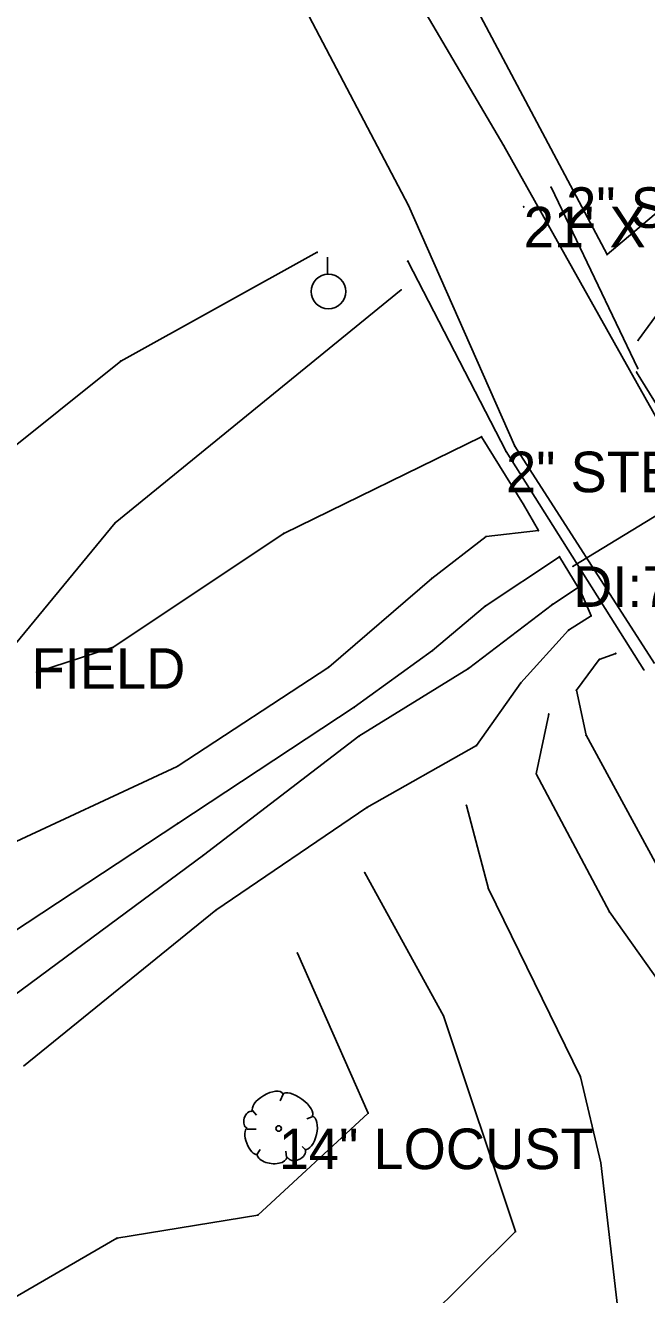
# Model space of a CAD drawing. Extents: x 1419505 to 1434054, y 1956910 to 1968644.
# Drawn here: x 1423011.2 to 1423087.7, y 1959040 to 1959196.4 of the extents above; entities that cross this region are included whole.
import ezdxf

# ---------------------------------------------------------------- set-up
doc = ezdxf.new("R2010")
doc.units = 0
for name, color, linetype in [('S_BREAKLINE', 7, 'Continuous'), ('S_DITCHLINE', 7, 'Continuous'), ('S_DRG_PT_SYM', 7, 'Continuous'), ('S_FENCE', 7, 'Continuous'), ('S_FENCE_ANNOT', 7, 'Continuous'), ('S_GATE_ANNOT', 7, 'Continuous'), ('S_GRAVEL_ROAD', 7, 'Continuous'), ('S_GRD_PT_SYM', 7, 'Continuous'), ('S_HEADWALL', 7, 'Continuous'), ('S_MSC_PT_SYM', 7, 'Continuous'), ('S_RDW_PT_SYM', 7, 'Continuous'), ('S_SIDE_DRAIN', 7, 'Continuous'), ('S_SIDE_DRAIN_ANNOT', 7, 'Continuous'), ('S_SURVEY_TEXT_ANNOT', 7, 'Continuous'), ('S_TREE', 7, 'Continuous'), ('S_TREE_ANNOT', 7, 'Continuous'), ('S_UTILITY_POLE', 7, 'Continuous')]:
    doc.layers.add(name, color=color, linetype=linetype)

msp = doc.modelspace()

# ---------------------------------------------------------------- linework, layer by layer
at = {"layer": 'S_BREAKLINE'}
for p, q in [((1423066.9272, 1959198.1301), (1423082.8213, 1959168.1511)), ((1423082.8213, 1959168.1511), (1423102.5315, 1959184.7692)), ((1423086.6625, 1959157.5914), (1423098.1723, 1959173.3905)), ((1423022.9164, 1959155.0183), (1423047.126, 1959168.4171)), ((1423022.2564, 1959135.109), (1423057.4626, 1959163.7828)), ((1422994.5276, 1959132.2688), (1423022.9164, 1959155.0183)), ((1423067.3583, 1959145.7077), (1423042.9967, 1959133.7819)), ((1423072.5376, 1959137.3621), (1423067.3583, 1959145.7077)), ((1423074.3627, 1959134.1599), (1423072.5376, 1959137.3621)), ((1422998.6778, 1959106.5561), (1423022.2564, 1959135.109)), ((1423042.9967, 1959133.7819), (1423022.0103, 1959119.77)), ((1423061.2399, 1959128.2445), (1423067.9153, 1959133.4009)), ((1423067.9153, 1959133.4009), (1423074.3627, 1959134.1599)), ((1423048.5511, 1959117.3138), (1423061.2399, 1959128.2445)), ((1423080.8521, 1959123.6222), (1423079.7661, 1959126.2424)), ((1423078.088, 1959121.8761), (1423080.8521, 1959123.6222)), ((1423072.2056, 1959115.3877), (1423078.088, 1959121.8761)), ((1423022.0103, 1959119.77), (1423012.5577, 1959116.6958)), ((1423081.8662, 1959118.2619), (1423083.9013, 1959119.0109)), ((1423029.8858, 1959105.094), (1423048.5511, 1959117.3138)), ((1423079.056, 1959114.4817), (1423081.8662, 1959118.2619)), ((1423066.7272, 1959107.6562), (1423072.2056, 1959115.3877)), ((1423080.2391, 1959108.9373), (1423079.056, 1959114.4817)), ((1423074.1077, 1959104.179), (1423075.6348, 1959111.5295)), ((1423089.7787, 1959091.4022), (1423080.2391, 1959108.9373)), ((1423053.2464, 1959100.0337), (1423066.7272, 1959107.6562)), ((1423000.908, 1959091.6272), (1423029.8858, 1959105.094)), ((1423083.1143, 1959087.1749), (1423074.1077, 1959104.179)), ((1423034.6522, 1959087.3959), (1423053.2464, 1959100.0337)), ((1423068.2213, 1959090.0191), (1423065.4961, 1959100.2827)), ((1423062.699, 1959074.3631), (1423052.9783, 1959092.0002)), ((1423079.5501, 1959066.8446), (1423068.2213, 1959090.0191)), ((1423010.9586, 1959068.1907), (1423034.6522, 1959087.3959)), ((1423097.3592, 1959067.1286), (1423083.1143, 1959087.1749)), ((1423053.4184, 1959062.4033), (1423044.6818, 1959082.1046)), ((1423071.5395, 1959047.7953), (1423062.699, 1959074.3631)), ((1423082.0782, 1959056.2559), (1423079.5501, 1959066.8446)), ((1423039.8265, 1959049.8425), (1423053.4184, 1959062.4033)), ((1423084.7974, 1959032.7634), (1423082.0782, 1959056.2559)), ((1423022.4534, 1959046.9853), (1423039.8265, 1959049.8425)), ((1422987.9141, 1959027.032), (1423022.4534, 1959046.9853)), ((1423056.3426, 1959032.7244), (1423071.5395, 1959047.7953))]:
    msp.add_line(p, q, dxfattribs=at)
at = {"layer": 'S_DITCHLINE'}
for p, q in [((1423076.9659, 1959130.9217), (1423067.8313, 1959124.8523)), ((1423079.284, 1959127.1275), (1423076.9659, 1959130.9217)), ((1423076.0958, 1959125.0493), (1423079.284, 1959127.1275)), ((1423065.7502, 1959117.1468), (1423076.0958, 1959125.0493)), ((1423067.8313, 1959124.8523), (1423061.3359, 1959119.361)), ((1423051.6803, 1959112.3905), (1423061.3409, 1959119.38)), ((1423052.2533, 1959108.8193), (1423065.7502, 1959117.1468)), ((1423029.9539, 1959098.0626), (1423051.6803, 1959112.3905)), ((1423033.1021, 1959094.1543), (1423052.2533, 1959108.8193)), ((1423001.755, 1959079.5054), (1423029.9539, 1959098.0626)), ((1423005.2653, 1959073.577), (1423033.1021, 1959094.1543))]:
    msp.add_line(p, q, dxfattribs=at)
at = {"layer": 'S_DRG_PT_SYM'}
msp.add_lwpolyline([(1423078.642, 1959129.7416), (1423078.642, 1959129.7916), (1423078.642, 1959129.7416), (1423078.592, 1959129.7416), (1423078.642, 1959129.7416), (1423078.642, 1959129.6916), (1423078.642, 1959129.7416), (1423078.692, 1959129.7416)], dxfattribs=at)
at = {"layer": 'S_FENCE'}
for p, q in [((1423075.9258, 1959176.4207), (1423086.5975, 1959154.1162)), ((1423070.3805, 1959143.8636), (1423058.2957, 1959167.3221))]:
    msp.add_line(p, q, dxfattribs=at)
at = {"layer": 'S_GRAVEL_ROAD'}
for p, q in [((1423070.1264, 1959181.533), (1423042.2936, 1959228.774)), ((1423058.3767, 1959174.1935), (1423036.7293, 1959215.3232)), ((1423101.5895, 1959125.3534), (1423070.1264, 1959181.533)), ((1423071.4495, 1959144.5446), (1423058.3767, 1959174.1935)), ((1423088.6566, 1959117.7649), (1423071.4495, 1959144.5446))]:
    msp.add_line(p, q, dxfattribs=at)
at = {"layer": 'S_GRD_PT_SYM'}
for points in [[(1423047.126, 1959168.4171), (1423047.126, 1959168.4671), (1423047.126, 1959168.4171), (1423047.076, 1959168.4171), (1423047.126, 1959168.4171), (1423047.126, 1959168.3671), (1423047.126, 1959168.4171), (1423047.176, 1959168.4171)], [(1423082.8213, 1959168.1511), (1423082.8213, 1959168.2011), (1423082.8213, 1959168.1511), (1423082.7713, 1959168.1511), (1423082.8213, 1959168.1511), (1423082.8213, 1959168.1011), (1423082.8213, 1959168.1511), (1423082.8713, 1959168.1511)], [(1423057.4626, 1959163.7828), (1423057.4626, 1959163.8328), (1423057.4626, 1959163.7828), (1423057.4126, 1959163.7828), (1423057.4626, 1959163.7828), (1423057.4626, 1959163.7328), (1423057.4626, 1959163.7828), (1423057.5126, 1959163.7828)], [(1423086.6625, 1959157.5914), (1423086.6625, 1959157.6414), (1423086.6625, 1959157.5914), (1423086.6125, 1959157.5914), (1423086.6625, 1959157.5914), (1423086.6625, 1959157.5414), (1423086.6625, 1959157.5914), (1423086.7125, 1959157.5914)], [(1423022.9164, 1959155.0183), (1423022.9164, 1959155.0683), (1423022.9164, 1959155.0183), (1423022.8664, 1959155.0183), (1423022.9164, 1959155.0183), (1423022.9164, 1959154.9683), (1423022.9164, 1959155.0183), (1423022.9664, 1959155.0183)], [(1423067.3583, 1959145.7077), (1423067.3583, 1959145.7577), (1423067.3583, 1959145.7077), (1423067.3083, 1959145.7077), (1423067.3583, 1959145.7077), (1423067.3583, 1959145.6577), (1423067.3583, 1959145.7077), (1423067.4083, 1959145.7077)], [(1423072.5376, 1959137.3621), (1423072.5376, 1959137.4121), (1423072.5376, 1959137.3621), (1423072.4876, 1959137.3621), (1423072.5376, 1959137.3621), (1423072.5376, 1959137.3121), (1423072.5376, 1959137.3621), (1423072.5876, 1959137.3621)], [(1423022.2564, 1959135.109), (1423022.2564, 1959135.159), (1423022.2564, 1959135.109), (1423022.2064, 1959135.109), (1423022.2564, 1959135.109), (1423022.2564, 1959135.059), (1423022.2564, 1959135.109), (1423022.3064, 1959135.109)], [(1423042.9967, 1959133.7819), (1423042.9967, 1959133.8319), (1423042.9967, 1959133.7819), (1423042.9467, 1959133.7819), (1423042.9967, 1959133.7819), (1423042.9967, 1959133.7319), (1423042.9967, 1959133.7819), (1423043.0467, 1959133.7819)], [(1423067.9153, 1959133.4009), (1423067.9153, 1959133.4509), (1423067.9153, 1959133.4009), (1423067.8653, 1959133.4009), (1423067.9153, 1959133.4009), (1423067.9153, 1959133.3509), (1423067.9153, 1959133.4009), (1423067.9653, 1959133.4009)], [(1423074.3627, 1959134.1599), (1423074.3627, 1959134.2099), (1423074.3627, 1959134.1599), (1423074.3127, 1959134.1599), (1423074.3627, 1959134.1599), (1423074.3627, 1959134.1099), (1423074.3627, 1959134.1599), (1423074.4127, 1959134.1599)], [(1423076.9659, 1959130.9217), (1423076.9659, 1959130.9717), (1423076.9659, 1959130.9217), (1423076.9159, 1959130.9217), (1423076.9659, 1959130.9217), (1423076.9659, 1959130.8717), (1423076.9659, 1959130.9217), (1423077.0159, 1959130.9217)], [(1423061.2399, 1959128.2445), (1423061.2399, 1959128.2945), (1423061.2399, 1959128.2445), (1423061.1899, 1959128.2445), (1423061.2399, 1959128.2445), (1423061.2399, 1959128.1945), (1423061.2399, 1959128.2445), (1423061.2899, 1959128.2445)], [(1423079.284, 1959127.1275), (1423079.284, 1959127.1775), (1423079.284, 1959127.1275), (1423079.234, 1959127.1275), (1423079.284, 1959127.1275), (1423079.284, 1959127.0775), (1423079.284, 1959127.1275), (1423079.334, 1959127.1275)], [(1423067.8313, 1959124.8523), (1423067.8313, 1959124.9023), (1423067.8313, 1959124.8523), (1423067.7813, 1959124.8523), (1423067.8313, 1959124.8523), (1423067.8313, 1959124.8023), (1423067.8313, 1959124.8523), (1423067.8813, 1959124.8523)], [(1423076.0958, 1959125.0493), (1423076.0958, 1959125.0993), (1423076.0958, 1959125.0493), (1423076.0458, 1959125.0493), (1423076.0958, 1959125.0493), (1423076.0958, 1959124.9993), (1423076.0958, 1959125.0493), (1423076.1458, 1959125.0493)], [(1423079.7661, 1959126.2424), (1423079.7661, 1959126.2924), (1423079.7661, 1959126.2424), (1423079.7161, 1959126.2424), (1423079.7661, 1959126.2424), (1423079.7661, 1959126.1924), (1423079.7661, 1959126.2424), (1423079.8161, 1959126.2424)], [(1423080.8521, 1959123.6222), (1423080.8521, 1959123.6722), (1423080.8521, 1959123.6222), (1423080.8021, 1959123.6222), (1423080.8521, 1959123.6222), (1423080.8521, 1959123.5722), (1423080.8521, 1959123.6222), (1423080.9021, 1959123.6222)], [(1423078.088, 1959121.8761), (1423078.088, 1959121.9261), (1423078.088, 1959121.8761), (1423078.038, 1959121.8761), (1423078.088, 1959121.8761), (1423078.088, 1959121.8261), (1423078.088, 1959121.8761), (1423078.138, 1959121.8761)], [(1423022.0103, 1959119.77), (1423022.0103, 1959119.82), (1423022.0103, 1959119.77), (1423021.9603, 1959119.77), (1423022.0103, 1959119.77), (1423022.0103, 1959119.72), (1423022.0103, 1959119.77), (1423022.0603, 1959119.77)], [(1423061.3359, 1959119.361), (1423061.3359, 1959119.411), (1423061.3359, 1959119.361), (1423061.2859, 1959119.361), (1423061.3359, 1959119.361), (1423061.3359, 1959119.311), (1423061.3359, 1959119.361), (1423061.3859, 1959119.361)], [(1423061.3409, 1959119.38), (1423061.3409, 1959119.43), (1423061.3409, 1959119.38), (1423061.2909, 1959119.38), (1423061.3409, 1959119.38), (1423061.3409, 1959119.33), (1423061.3409, 1959119.38), (1423061.3909, 1959119.38)], [(1423083.9013, 1959119.0109), (1423083.9013, 1959119.0609), (1423083.9013, 1959119.0109), (1423083.8513, 1959119.0109), (1423083.9013, 1959119.0109), (1423083.9013, 1959118.9609), (1423083.9013, 1959119.0109), (1423083.9513, 1959119.0109)], [(1423048.5511, 1959117.3138), (1423048.5511, 1959117.3638), (1423048.5511, 1959117.3138), (1423048.5011, 1959117.3138), (1423048.5511, 1959117.3138), (1423048.5511, 1959117.2638), (1423048.5511, 1959117.3138), (1423048.6011, 1959117.3138)], [(1423065.7502, 1959117.1468), (1423065.7502, 1959117.1968), (1423065.7502, 1959117.1468), (1423065.7002, 1959117.1468), (1423065.7502, 1959117.1468), (1423065.7502, 1959117.0968), (1423065.7502, 1959117.1468), (1423065.8002, 1959117.1468)], [(1423081.8662, 1959118.2619), (1423081.8662, 1959118.3119), (1423081.8662, 1959118.2619), (1423081.8162, 1959118.2619), (1423081.8662, 1959118.2619), (1423081.8662, 1959118.2119), (1423081.8662, 1959118.2619), (1423081.9162, 1959118.2619)], [(1423012.5577, 1959116.6958), (1423012.5577, 1959116.7458), (1423012.5577, 1959116.6958), (1423012.5077, 1959116.6958), (1423012.5577, 1959116.6958), (1423012.5577, 1959116.6458), (1423012.5577, 1959116.6958), (1423012.6077, 1959116.6958)], [(1423072.2056, 1959115.3877), (1423072.2056, 1959115.4377), (1423072.2056, 1959115.3877), (1423072.1556, 1959115.3877), (1423072.2056, 1959115.3877), (1423072.2056, 1959115.3377), (1423072.2056, 1959115.3877), (1423072.2556, 1959115.3877)], [(1423079.056, 1959114.4817), (1423079.056, 1959114.5317), (1423079.056, 1959114.4817), (1423079.006, 1959114.4817), (1423079.056, 1959114.4817), (1423079.056, 1959114.4317), (1423079.056, 1959114.4817), (1423079.106, 1959114.4817)], [(1423051.6803, 1959112.3905), (1423051.6803, 1959112.4405), (1423051.6803, 1959112.3905), (1423051.6303, 1959112.3905), (1423051.6803, 1959112.3905), (1423051.6803, 1959112.3405), (1423051.6803, 1959112.3905), (1423051.7303, 1959112.3905)], [(1423075.6348, 1959111.5295), (1423075.6348, 1959111.5795), (1423075.6348, 1959111.5295), (1423075.5848, 1959111.5295), (1423075.6348, 1959111.5295), (1423075.6348, 1959111.4795), (1423075.6348, 1959111.5295), (1423075.6848, 1959111.5295)], [(1423052.2533, 1959108.8193), (1423052.2533, 1959108.8693), (1423052.2533, 1959108.8193), (1423052.2033, 1959108.8193), (1423052.2533, 1959108.8193), (1423052.2533, 1959108.7693), (1423052.2533, 1959108.8193), (1423052.3033, 1959108.8193)], [(1423066.7272, 1959107.6562), (1423066.7272, 1959107.7062), (1423066.7272, 1959107.6562), (1423066.6772, 1959107.6562), (1423066.7272, 1959107.6562), (1423066.7272, 1959107.6062), (1423066.7272, 1959107.6562), (1423066.7772, 1959107.6562)], [(1423080.2391, 1959108.9373), (1423080.2391, 1959108.9873), (1423080.2391, 1959108.9373), (1423080.1891, 1959108.9373), (1423080.2391, 1959108.9373), (1423080.2391, 1959108.8873), (1423080.2391, 1959108.9373), (1423080.2891, 1959108.9373)], [(1423029.8858, 1959105.094), (1423029.8858, 1959105.144), (1423029.8858, 1959105.094), (1423029.8358, 1959105.094), (1423029.8858, 1959105.094), (1423029.8858, 1959105.044), (1423029.8858, 1959105.094), (1423029.9358, 1959105.094)], [(1423074.1077, 1959104.179), (1423074.1077, 1959104.229), (1423074.1077, 1959104.179), (1423074.0577, 1959104.179), (1423074.1077, 1959104.179), (1423074.1077, 1959104.129), (1423074.1077, 1959104.179), (1423074.1577, 1959104.179)], [(1423053.2464, 1959100.0337), (1423053.2464, 1959100.0837), (1423053.2464, 1959100.0337), (1423053.1964, 1959100.0337), (1423053.2464, 1959100.0337), (1423053.2464, 1959099.9837), (1423053.2464, 1959100.0337), (1423053.2964, 1959100.0337)], [(1423065.4961, 1959100.2827), (1423065.4961, 1959100.3327), (1423065.4961, 1959100.2827), (1423065.4461, 1959100.2827), (1423065.4961, 1959100.2827), (1423065.4961, 1959100.2327), (1423065.4961, 1959100.2827), (1423065.5461, 1959100.2827)], [(1423029.9539, 1959098.0626), (1423029.9539, 1959098.1126), (1423029.9539, 1959098.0626), (1423029.9039, 1959098.0626), (1423029.9539, 1959098.0626), (1423029.9539, 1959098.0126), (1423029.9539, 1959098.0626), (1423030.0039, 1959098.0626)], [(1423033.1021, 1959094.1543), (1423033.1021, 1959094.2043), (1423033.1021, 1959094.1543), (1423033.0521, 1959094.1543), (1423033.1021, 1959094.1543), (1423033.1021, 1959094.1043), (1423033.1021, 1959094.1543), (1423033.1521, 1959094.1543)], [(1423052.9783, 1959092.0002), (1423052.9783, 1959092.0502), (1423052.9783, 1959092.0002), (1423052.9283, 1959092.0002), (1423052.9783, 1959092.0002), (1423052.9783, 1959091.9502), (1423052.9783, 1959092.0002), (1423053.0283, 1959092.0002)], [(1423068.2213, 1959090.0191), (1423068.2213, 1959090.0691), (1423068.2213, 1959090.0191), (1423068.1713, 1959090.0191), (1423068.2213, 1959090.0191), (1423068.2213, 1959089.9691), (1423068.2213, 1959090.0191), (1423068.2713, 1959090.0191)], [(1423034.6522, 1959087.3959), (1423034.6522, 1959087.4459), (1423034.6522, 1959087.3959), (1423034.6022, 1959087.3959), (1423034.6522, 1959087.3959), (1423034.6522, 1959087.3459), (1423034.6522, 1959087.3959), (1423034.7022, 1959087.3959)], [(1423083.1143, 1959087.1749), (1423083.1143, 1959087.2249), (1423083.1143, 1959087.1749), (1423083.0643, 1959087.1749), (1423083.1143, 1959087.1749), (1423083.1143, 1959087.1249), (1423083.1143, 1959087.1749), (1423083.1643, 1959087.1749)], [(1423044.6818, 1959082.1046), (1423044.6818, 1959082.1546), (1423044.6818, 1959082.1046), (1423044.6318, 1959082.1046), (1423044.6818, 1959082.1046), (1423044.6818, 1959082.0546), (1423044.6818, 1959082.1046), (1423044.7318, 1959082.1046)], [(1423062.699, 1959074.3631), (1423062.699, 1959074.4131), (1423062.699, 1959074.3631), (1423062.649, 1959074.3631), (1423062.699, 1959074.3631), (1423062.699, 1959074.3131), (1423062.699, 1959074.3631), (1423062.749, 1959074.3631)], [(1423079.5501, 1959066.8446), (1423079.5501, 1959066.8946), (1423079.5501, 1959066.8446), (1423079.5001, 1959066.8446), (1423079.5501, 1959066.8446), (1423079.5501, 1959066.7946), (1423079.5501, 1959066.8446), (1423079.6001, 1959066.8446)], [(1423053.4184, 1959062.4033), (1423053.4184, 1959062.4533), (1423053.4184, 1959062.4033), (1423053.3684, 1959062.4033), (1423053.4184, 1959062.4033), (1423053.4184, 1959062.3533), (1423053.4184, 1959062.4033), (1423053.4684, 1959062.4033)], [(1423082.0782, 1959056.2559), (1423082.0782, 1959056.3059), (1423082.0782, 1959056.2559), (1423082.0282, 1959056.2559), (1423082.0782, 1959056.2559), (1423082.0782, 1959056.2059), (1423082.0782, 1959056.2559), (1423082.1282, 1959056.2559)], [(1423039.8265, 1959049.8425), (1423039.8265, 1959049.8925), (1423039.8265, 1959049.8425), (1423039.7765, 1959049.8425), (1423039.8265, 1959049.8425), (1423039.8265, 1959049.7925), (1423039.8265, 1959049.8425), (1423039.8765, 1959049.8425)], [(1423022.4534, 1959046.9853), (1423022.4534, 1959047.0353), (1423022.4534, 1959046.9853), (1423022.4034, 1959046.9853), (1423022.4534, 1959046.9853), (1423022.4534, 1959046.9353), (1423022.4534, 1959046.9853), (1423022.5034, 1959046.9853)], [(1423071.5395, 1959047.7953), (1423071.5395, 1959047.8453), (1423071.5395, 1959047.7953), (1423071.4895, 1959047.7953), (1423071.5395, 1959047.7953), (1423071.5395, 1959047.7453), (1423071.5395, 1959047.7953), (1423071.5895, 1959047.7953)]]:
    msp.add_lwpolyline(points, dxfattribs=at)
at = {"layer": 'S_HEADWALL'}
for p, q in [((1423103.2646, 1959126.2634), (1423086.4725, 1959153.6502)), ((1423087.3686, 1959116.9998), (1423070.3825, 1959143.8816))]:
    msp.add_line(p, q, dxfattribs=at)
at = {"layer": 'S_MSC_PT_SYM'}
for points in [[(1423075.9258, 1959176.4207), (1423075.9258, 1959176.4707), (1423075.9258, 1959176.4207), (1423075.8758, 1959176.4207), (1423075.9258, 1959176.4207), (1423075.9258, 1959176.3707), (1423075.9258, 1959176.4207), (1423075.9758, 1959176.4207)], [(1423072.5606, 1959174.0225), (1423072.5606, 1959174.0725), (1423072.5606, 1959174.0225), (1423072.5106, 1959174.0225), (1423072.5606, 1959174.0225), (1423072.5606, 1959173.9725), (1423072.5606, 1959174.0225), (1423072.6106, 1959174.0225)], [(1423058.2957, 1959167.3221), (1423058.2957, 1959167.3721), (1423058.2957, 1959167.3221), (1423058.2457, 1959167.3221), (1423058.2957, 1959167.3221), (1423058.2957, 1959167.2721), (1423058.2957, 1959167.3221), (1423058.3457, 1959167.3221)], [(1423086.4725, 1959153.6502), (1423086.4725, 1959153.7002), (1423086.4725, 1959153.6502), (1423086.4225, 1959153.6502), (1423086.4725, 1959153.6502), (1423086.4725, 1959153.6002), (1423086.4725, 1959153.6502), (1423086.5225, 1959153.6502)], [(1423086.5975, 1959154.1162), (1423086.5975, 1959154.1662), (1423086.5975, 1959154.1162), (1423086.5475, 1959154.1162), (1423086.5975, 1959154.1162), (1423086.5975, 1959154.0662), (1423086.5975, 1959154.1162), (1423086.6475, 1959154.1162)], [(1423070.3805, 1959143.8636), (1423070.3805, 1959143.9136), (1423070.3805, 1959143.8636), (1423070.3305, 1959143.8636), (1423070.3805, 1959143.8636), (1423070.3805, 1959143.8136), (1423070.3805, 1959143.8636), (1423070.4305, 1959143.8636)], [(1423070.3825, 1959143.8816), (1423070.3825, 1959143.9316), (1423070.3825, 1959143.8816), (1423070.3325, 1959143.8816), (1423070.3825, 1959143.8816), (1423070.3825, 1959143.8316), (1423070.3825, 1959143.8816), (1423070.4325, 1959143.8816)], [(1423087.3686, 1959116.9998), (1423087.3686, 1959117.0498), (1423087.3686, 1959116.9998), (1423087.3186, 1959116.9998), (1423087.3686, 1959116.9998), (1423087.3686, 1959116.9498), (1423087.3686, 1959116.9998), (1423087.4186, 1959116.9998)]]:
    msp.add_lwpolyline(points, dxfattribs=at)
at = {"layer": 'S_RDW_PT_SYM'}
for points in [[(1423070.1264, 1959181.533), (1423070.1264, 1959181.583), (1423070.1264, 1959181.533), (1423070.0764, 1959181.533), (1423070.1264, 1959181.533), (1423070.1264, 1959181.483), (1423070.1264, 1959181.533), (1423070.1764, 1959181.533)], [(1423058.3767, 1959174.1935), (1423058.3767, 1959174.2435), (1423058.3767, 1959174.1935), (1423058.3267, 1959174.1935), (1423058.3767, 1959174.1935), (1423058.3767, 1959174.1435), (1423058.3767, 1959174.1935), (1423058.4267, 1959174.1935)], [(1423071.4495, 1959144.5446), (1423071.4495, 1959144.5946), (1423071.4495, 1959144.5446), (1423071.3995, 1959144.5446), (1423071.4495, 1959144.5446), (1423071.4495, 1959144.4946), (1423071.4495, 1959144.5446), (1423071.4995, 1959144.5446)]]:
    msp.add_lwpolyline(points, dxfattribs=at)
at = {"layer": 'S_SIDE_DRAIN'}
msp.add_line((1423078.642, 1959129.7416), (1423095.3371, 1959139.9373), dxfattribs=at)
at = {"layer": 'S_TREE'}
for p, q in [((1423042.9386, 1959064.7397), (1423042.5511, 1959063.8872)), ((1423039.1411, 1959062.7247), (1423039.6449, 1959062.1434)), ((1423046.5036, 1959061.9497), (1423045.8449, 1959061.6784)), ((1423038.4824, 1959060.3997), (1423039.6061, 1959060.3997)), ((1423039.6449, 1959057.2222), (1423040.1099, 1959057.9197)), ((1423043.3261, 1959056.9509), (1423043.2486, 1959057.7259)), ((1423045.7286, 1959057.8422), (1423045.2636, 1959058.2684))]:
    msp.add_line(p, q, dxfattribs=at)
msp.add_circle((1423042.3807, 1959060.4942), 0.3405, dxfattribs=at)
for centre, major_axis, ratio, start_param, end_param in [((1423041.0443, 1959063.6965), (1.8569, 1.0848), 0.47101751, 0.00000015, 3.1415928), ((1423044.6992, 1959063.3732), (-1.8132, 1.3599), 0.40511279, 3.1415929, 6.28318555), ((1423038.8099, 1959061.5818), (0.3053, 1.0268), 0.6467619, 0.0000001, 3.14159275), ((1423046.0544, 1959059.9642), (0.4579, 2.0398), 0.48299385, 3.1415928, 6.28318545), ((1423039.1151, 1959058.9314), (-0.6105, 1.5958), 0.42054324, 6.28318458, 9.42477723), ((1423044.5328, 1959057.4435), (1.0915, 0.4624), 0.71153436, 3.14159246, 6.28318511), ((1423041.5758, 1959057.1507), (-1.8316, 0.1942), 0.52994287, 0.00000019, 3.14159285)]:
    msp.add_ellipse(centre, major_axis=major_axis, ratio=ratio, start_param=start_param, end_param=end_param, dxfattribs=at)
at = {"layer": 'S_UTILITY_POLE'}
msp.add_line((1423048.3847, 1959165.727), (1423048.3847, 1959167.835), dxfattribs=at)
msp.add_circle((1423048.507, 1959163.5858), 2.1268, dxfattribs=at)

# ---------------------------------------------------------------- texts
at = {"layer": 'S_FENCE_ANNOT'}
for s, p in [(' 2" STEEL POST', (1423075.9258, 1959171.4207)), ('2" STEEL PIPE/ STEEL POST', (1423070.3805, 1959138.8636))]:
    msp.add_text(s, height=5, dxfattribs=at).set_placement(p)
at = {"layer": 'S_GATE_ANNOT'}
msp.add_text("21' X 4' STEEL", height=5, dxfattribs=at).set_placement((1423072.5606, 1959169.0225))
at = {"layer": 'S_SIDE_DRAIN_ANNOT'}
msp.add_text('DI:7.00 TY:STEEL TRAINCAR CN:10', height=5, dxfattribs=at).set_placement((1423078.642, 1959124.7416))
at = {"layer": 'S_SURVEY_TEXT_ANNOT'}
msp.add_text('CULTIVATED FIELD', height=5, dxfattribs=at).set_placement((1422968.4719, 1959114.654))
at = {"layer": 'S_TREE_ANNOT'}
msp.add_text('14" LOCUST', height=5, dxfattribs=at).set_placement((1423042.3807, 1959055.4942))

doc.saveas('drawing.dxf')
